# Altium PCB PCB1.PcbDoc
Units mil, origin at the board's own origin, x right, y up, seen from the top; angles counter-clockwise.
Board outline 6000 x 4000 mil, 2 copper layers (Top Layer, Bottom Layer); 7 components, 4 nets, 17 pads, 0 vias.
Unrouted connection lines stored in the file: 10.
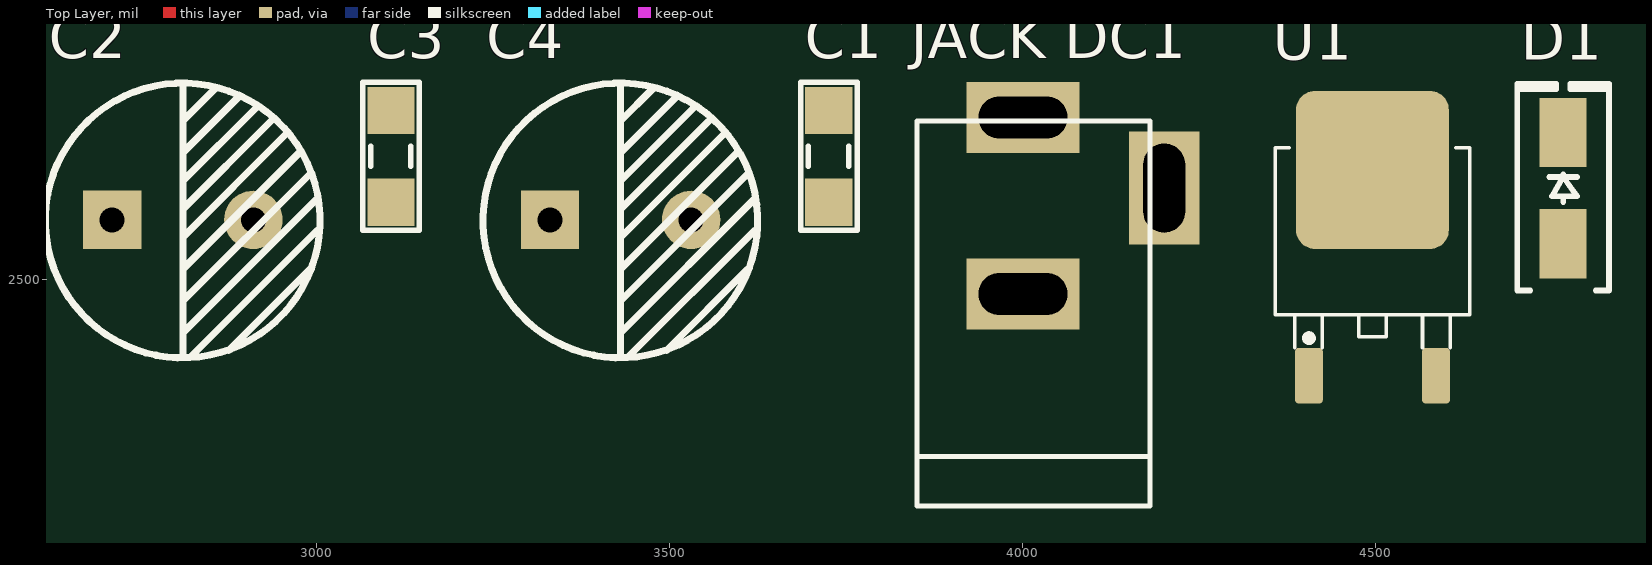
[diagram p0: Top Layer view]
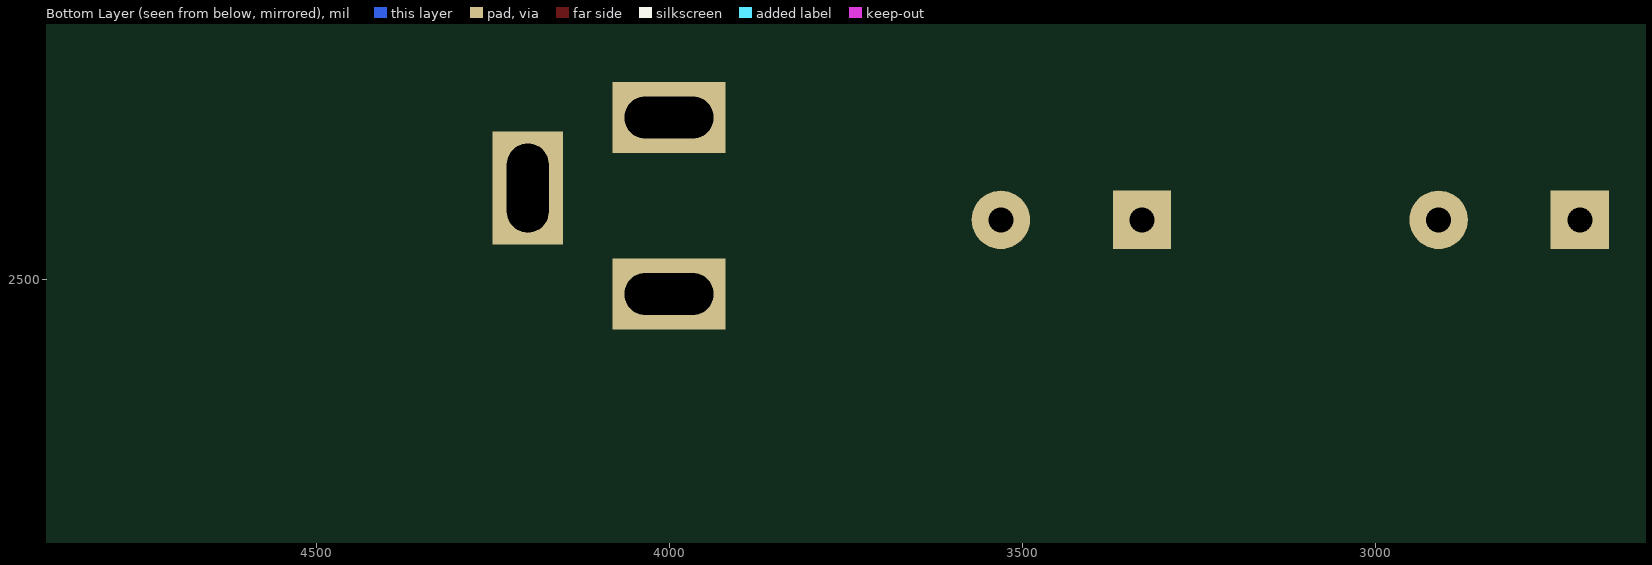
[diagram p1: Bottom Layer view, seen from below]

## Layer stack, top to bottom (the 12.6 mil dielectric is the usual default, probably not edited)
Top Solder: solder mask 0.4, Solder Resist, Dk 3.5
Top Layer: signal copper 1.4
Dielectric 1: dielectric 12.6, FR-4, Dk 4.8
Bottom Layer: signal copper 1.4
Bottom Solder: solder mask 0.4, Solder Resist, Dk 3.5

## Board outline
1000,1000 7000,1000 7000,5000 1000,5000

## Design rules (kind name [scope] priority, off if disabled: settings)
Clearance [All] p1: gap=10 ignorepadtopadclearanceinfootprint=FALSE except(0: Arc-Hole Track-Hole SMDPad-Hole THPad-Hole Via-Hole Fill-Hole Poly-Hole Region-Hole Text-Hole)
PolygonConnect [All] p1: connectstyle=Relief reliefconductorwidth=10 reliefentries=4 polygonreliefangle="90 Angle" airgapwidth=10
RoomDefinition LM7805 [InComponentClass('LM7805')] p1: confinementstyle=ConfineIn formatcopy=TRUE lockcomponents=FALSE outline 2605,2170 4840,2170 4840,2890 2605,2890
RoutingVias [All] p1: holewidth=28 width=50 viastyle="Through Hole" minholewidth=28 minwidth=50 maxholewidth=28 maxwidth=50
SolderMaskExpansion [All] p1: expansion=4 istentingtop=FALSE
Width [All] p1: maxlimit=10 minlimit=10 preferedwidth=10
30 further rules are at their usual default settings.

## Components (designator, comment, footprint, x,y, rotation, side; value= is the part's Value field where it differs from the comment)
C1 "104" "tu 1206" 3725,2675 r90 top
C2 "1500uF" "tu hoa 10mm" 2810,2585 r0 top
C3 "104" "tu 1206" 3105,2675 r90 top
C4 "1500uF" "tu hoa 10mm" 3430,2585 r0 top
D1 "M7" "DIODE SMA" 4765,2630 r90 top
"JACK DC1" "JACK DC 12V" "JACK DC 5.5" 4100,2605 r90 top value="Jac DC"
U1 "78M05 SMD TO252" TO252 4495,2510 r0 top

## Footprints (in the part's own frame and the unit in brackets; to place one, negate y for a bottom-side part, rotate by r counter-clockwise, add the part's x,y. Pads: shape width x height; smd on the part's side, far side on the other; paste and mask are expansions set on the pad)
"DIODE SMA" [mm] "SMA"
  rect 2.5x1.7 smd: 1(-2,0) 2(2,0)
  silkscreen extent -3.68,-1.65 3.75,1.65, body extent -2.6,-1.37 2.6,1.37, height 2.4
"JACK DC 5.5" [mil] "Jac DC input"
  rect 100x160 hole 59.06 slot 125.98 at 90 deg: 1(125,100) 2(-125,100)
  rect 160x100 hole 59.06 slot 125.98 at 0 deg: 3(25,-100)
  silkscreen extent -425,-80 120,250, body extent -410,-105 134,269, height 434
TO252 [mm] "TO252"
  round 0.5 on Mech15: 0(0,0)
  rrect25% 1x2 smd: 1(-2.285,-3.7) 3(2.285,-3.7)
  rrect25% 5.5x5.7 smd: 2(0,3.7)
  silkscreen extent -3.5,-2.7 3.5,4.5, body extent -3.3,-3.95 3.3,5.76, height 2.31
"tu 1206" [mm]
  rect 1.7x1.7 smd: 1(-1.65,0) 2(1.65,0)
  silkscreen extent -2.67,-1.02 2.67,1.02, body extent -1.57,-0.8 1.63,0.8, height 0.94
"tu hoa 10mm" [mm]
  rect 2.1x2.1 hole 0.9: 1(-2.54,0)
  round 2.1 hole 0.9: 2(2.54,0)
  silkscreen extent -4.95,-4.96 4.93,4.92, body extent -5,-5 4.97,5, height 20.01

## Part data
C1 C3: library part "Tu 1206 104 50V 20%", "Dán"
C2 C4: library part "Tu Hoa 1500uF 16V 10x20", "Cắm"
D1: library part "Diode M7 ( 4007 )", "Dán"
"JACK DC1": library part "JACK DC 5.5", "JACK DC 5.5"
U1: "Dán"

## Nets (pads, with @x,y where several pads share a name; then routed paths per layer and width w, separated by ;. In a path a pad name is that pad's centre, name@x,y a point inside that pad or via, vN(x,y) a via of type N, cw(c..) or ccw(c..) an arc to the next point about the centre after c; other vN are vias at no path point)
GND: "JACK DC1.2" C1.1 C2.2 C3.1 C4.2 U1.2
NetC1_2: C1.2 D1.2 U1.1
NetC3_2: C3.2 C4.1 U1.3
NetD1_1: "JACK DC1.1" D1.1
pads on no net: "JACK DC1.3" C2.1 U1.0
